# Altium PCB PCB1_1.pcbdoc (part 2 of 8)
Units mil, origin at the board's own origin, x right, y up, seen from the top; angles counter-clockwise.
Board outline 3937.01 x 3346.46 mil, 6 copper layers (Top Layer, Signal-1, SIG, POWER, Signal-4, Bottom Layer), stack 60.565 mil thick; 256 components, 201 nets, 1360 pads, 815 vias.
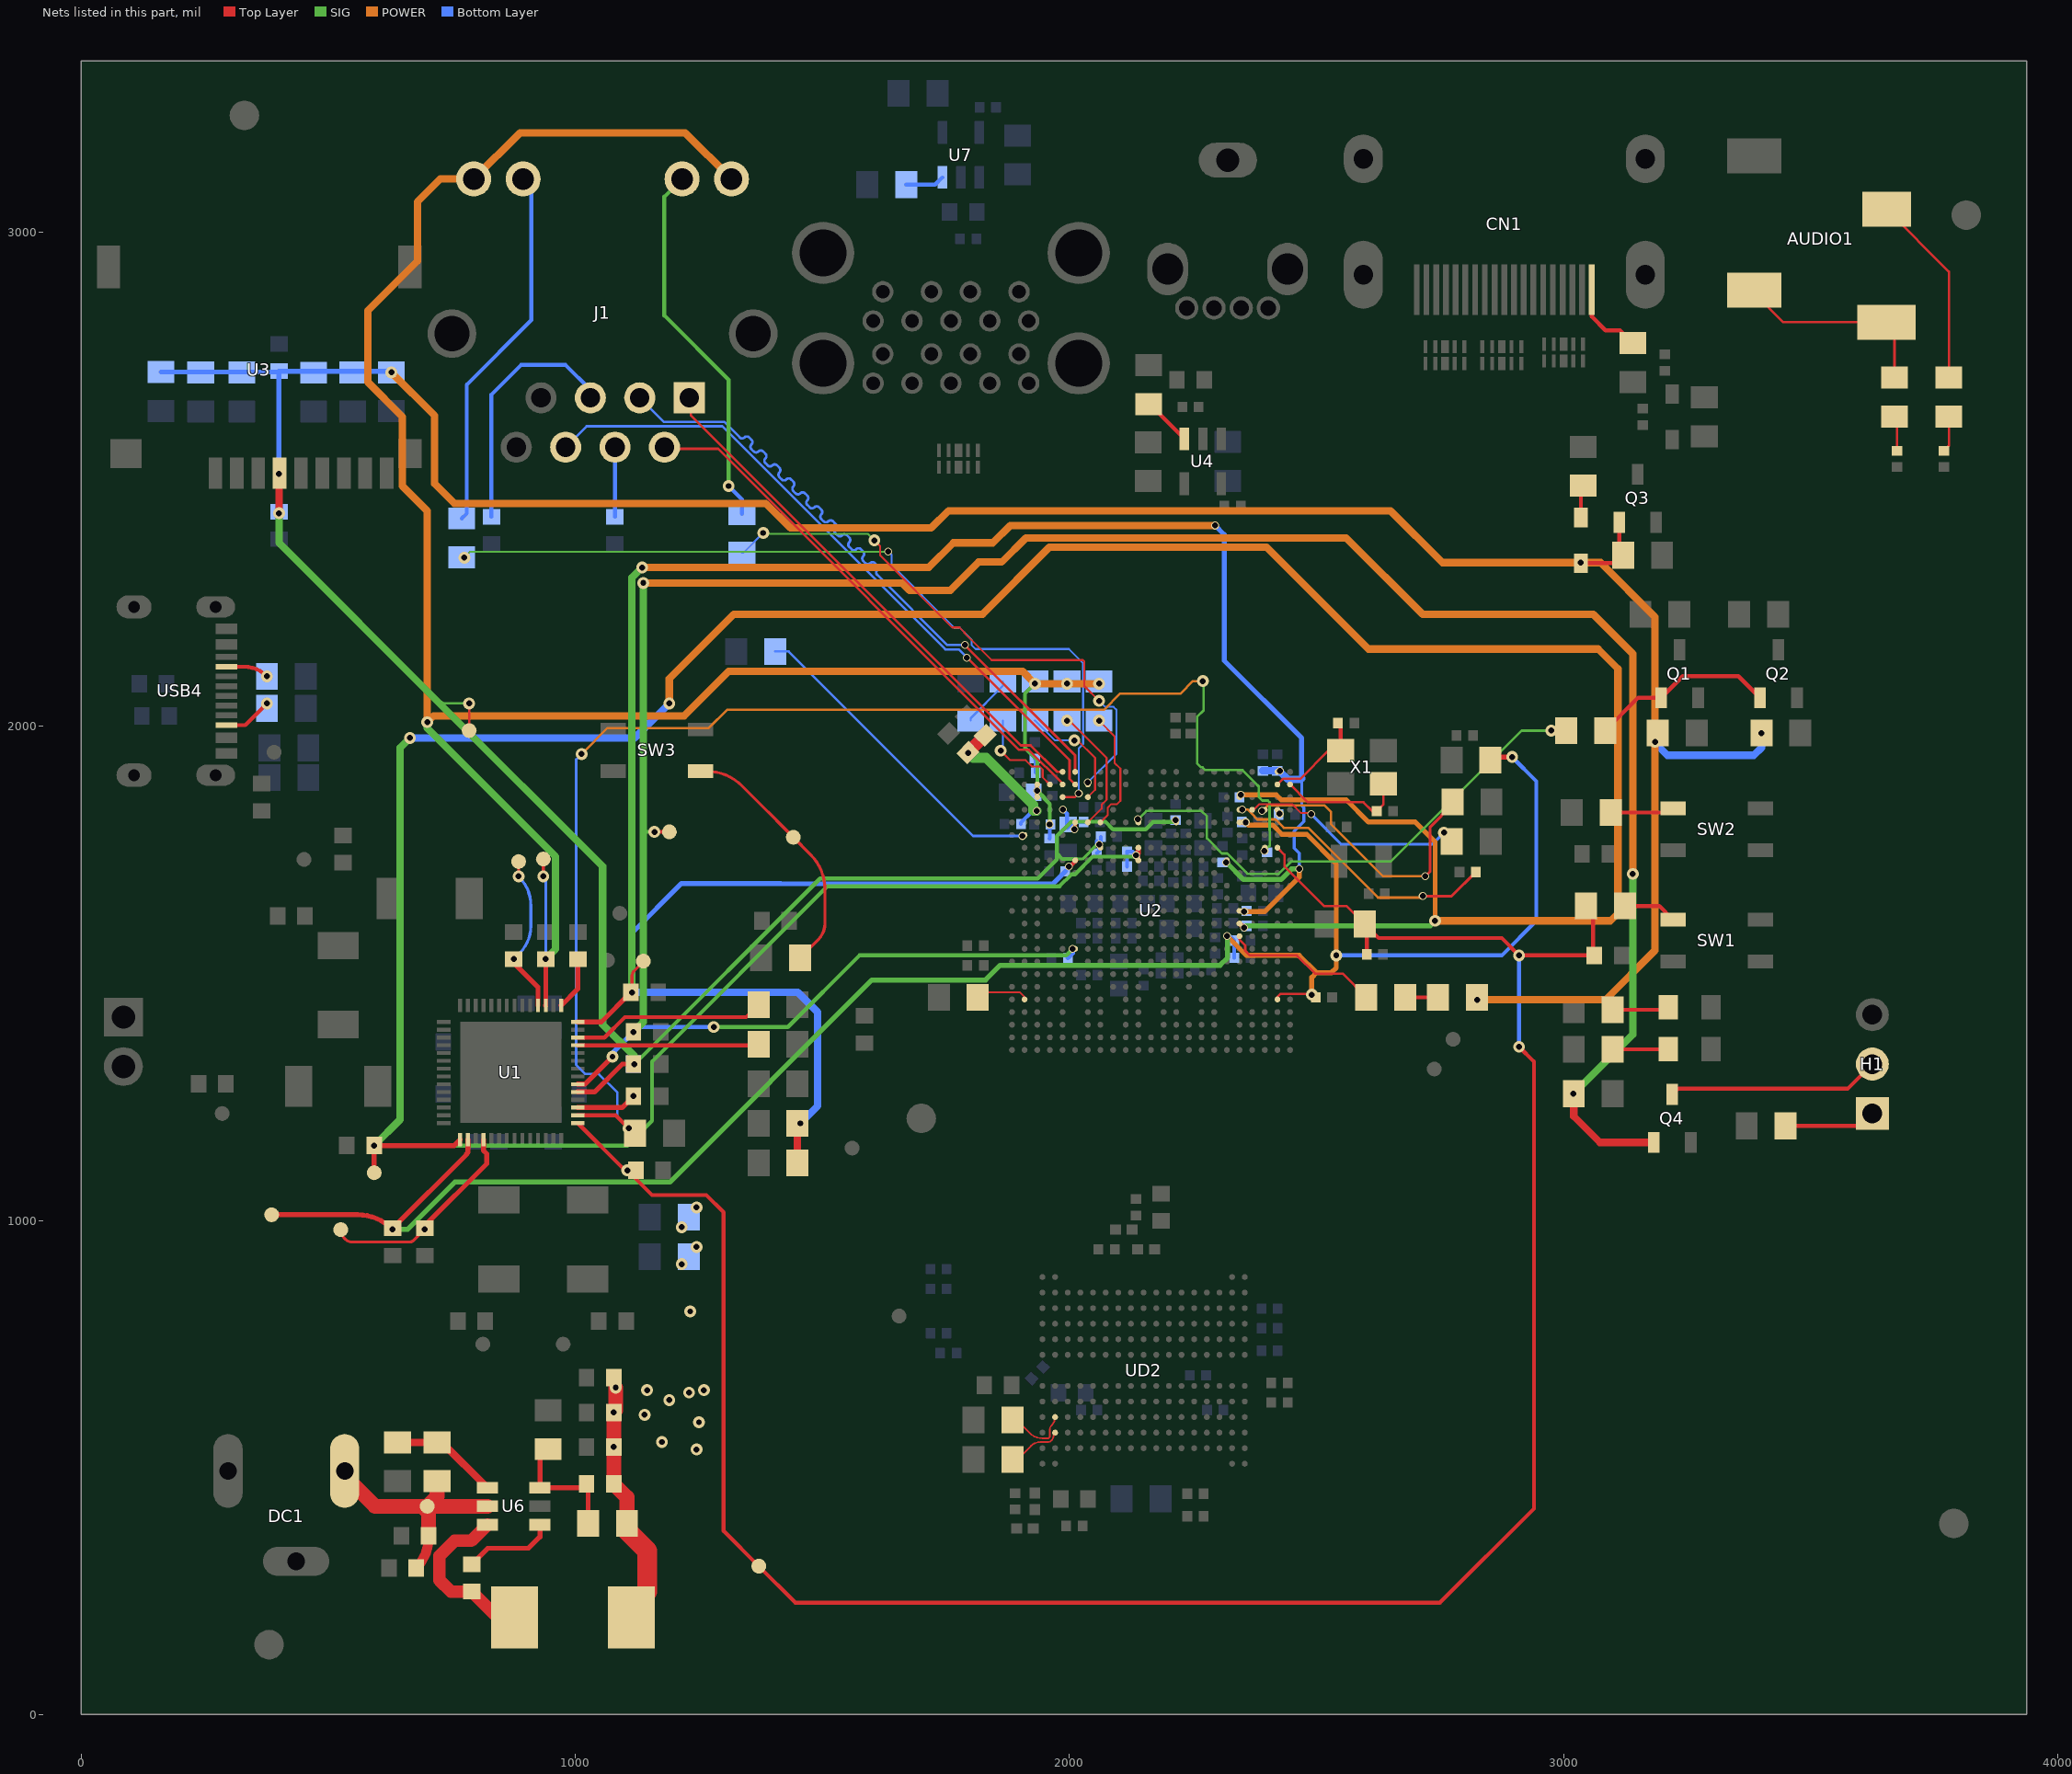
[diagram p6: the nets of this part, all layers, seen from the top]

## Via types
v1: diameter 16, hole 12, Top Layer to Bottom Layer, 426 vias
v2: diameter 24, hole 12, Top Layer to Bottom Layer, 385 vias
v3: diameter 34, hole 12, Top Layer to Bottom Layer, 2 vias
v4: diameter 30, hole 12, Top Layer to Bottom Layer, 2 vias

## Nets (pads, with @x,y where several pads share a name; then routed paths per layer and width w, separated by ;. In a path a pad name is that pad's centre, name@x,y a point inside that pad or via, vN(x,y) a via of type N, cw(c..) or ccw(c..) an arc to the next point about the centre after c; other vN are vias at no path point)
$1N47: R17.2 U2.W2 | length 108.9
  Top Layer w4: R17.2@1814.37,1451.46 1814.37,1453.22 1823.16,1462.01 1899.08,1462.01 1909.09,1451.99 U2.W2@1909.09,1447.36
$1N119: R18.1 UD2.B3 | length 110.3
  Top Layer w3.5: R18.1@1884.37,516.46 ccw(c1884.37,542.12) 1902.52,523.97 1922.27,543.73 cw(c1940.93,525.08) 1940.93,551.46 1951.78,551.46 ccw(c1951.78,551.62) 1951.9,551.5 1955.78,551.48 ccw(c1955.78,563.21) 1964.07,554.92 ccw(c1955.78,563.21) 1967.5,563.21 cw(c1976.91,563.21) 1970.26,569.86 UD2.B3@1970.87,570.47
$1N172: R30.1 UD2.B4 | length 132.8
  Top Layer w3.5: R30.1@1884.37,596.46 cw(c1884.37,576.77) 1898.29,590.69 1919.39,569.59 ccw(c1945,595.2) 1945,558.98 1955.78,558.98 ccw(c1955.78,563.21) 1958.76,560.22 ccw(c1955.78,563.21) 1960,563.21 1960,575.74 cw(c1973.81,575.74) 1964.05,585.5 ccw(c1947.58,601.97) UD2.B4@1970.87,601.97
$2N7: C137.2 J1.4 | length 141.1
  Bottom Layer w8: C137.2@1080,2424.02 1080,2564.8 J1.4@1080.2,2565
$2N9: C138.2 J1.5 | length 509.5
  Bottom Layer w8: C138.2@830,2424.02 830,2671.46 890,2731.46 980,2731.46 1030.2,2681.26 J1.5@1030.2,2665
$2N15: J1.10 R45.2 | length 757.9
  SIG w8: J1.10@1215.83,3107.91 1180,3072.08 1180,2831.46 1310,2701.46 v2(1310,2486.46)
  Bottom Layer w8: v2(1310,2486.46) 1337.04,2459.42 R45.2@1337.04,2429.91
$2N16: J1.11 R46.2 | length 752.3
  Bottom Layer w8: R46.2@770,2420.83 780,2430.83 780,2691.46 910.77,2822.23 910.77,3091.31 J1.11@894.17,3107.91
$2N51: CN1.19 R47.2 | length 159.9
  Top Layer w8: CN1.19@3057.15,2884.17 3057.15,2829.3 3085,2801.46 3114.37,2801.46 R47.2@3140,2775.83
$2N63: Q1.1 Q2.1 R48.2 | length 376.9
  Top Layer w8: R48.2@3084.37,1991.46 3150.74,2057.83 Q1.1@3197.6,2057.83 3241.23,2101.46 3353.98,2101.46 Q2.1@3397.6,2057.83
$2N73: D4.1 R54.2 | length 66.5
  Top Layer w8: D4.1@3035,2422.62 3035,2482.09 R54.2@3040,2487.09
$3N65: R4.2 U1.25 | length 366.6
  Top Layer w8: U1.25@1004.84,1354.46 1368.63,1354.46 R4.2@1370.63,1356.46
$3N68: R5.2 U1.26 | length 393.2
  Top Layer w8: U1.26@1004.84,1370.21 1058.75,1370.21 1100,1411.46 1345.63,1411.46 R5.2@1370.63,1436.46
$3N119: C25.1 U1.29 | length 107.7
  Top Layer w10: U1.29@971.38,1435.16 1005,1468.78 C25.1@1005,1528.9
$4N2: R8.2 R12.1 | length 66.3
  Top Layer w8: R12.1@2679.37,1451.46 R8.2@2745.63,1451.46
$4N5: R12.2 U2.P19 | length 318.3
  Top Layer w5: U2.P19@2344.13,1575.28 2344.13,1568.2 2355.54,1556.8 2355.54,1545.92 2365,1536.46 2460,1536.46 2497,1499.46 2552.63,1499.46 R12.2@2600.63,1451.46
$4N31: R23.1 U2.F2 | length 655.5
  Bottom Layer w5: R23.1@1404.28,2151.58 1431.62,2151.58 1805,1778.19 v1(1905.11,1778.19)
$5N38: R66.2 U2.B4 | length 200.1
  Top Layer w4: v2(1860.62,1950.84) 1880,1931.46 1911.18,1931.46 1923.78,1918.86 1939.2,1918.86 1945.59,1912.47 1945.59,1897.05 U2.B4@1960.28,1882.36
  Bottom Layer w4: v2(1860.62,1950.84) 1865,1955.22 R66.2@1865,2012.09
$5N74: R9.1 U2.E8 | length 247.3
  Top Layer w4: v2(2060,2011.46) 2091.5,1979.96 2091.5,1925.86 2102.91,1914.45 2102.91,1849.37 2095.63,1842.09 2083.71,1842.09 2077.32,1835.7 2077.32,1820.28 U2.E8@2062.64,1805.59
$5N75: R10.1 U2.C7 | length 238.8
  Top Layer w4: v2(2010,1971.46) 2016.73,1971.46 2051.73,1936.46 2051.73,1871.46 U2.C7@2037.05,1856.77
  Bottom Layer w4: R10.1@1930,2012.09 1970.63,1971.46 v2(2010,1971.46)
$5N76: R1.1 U2.E7 | length 257.7
  Top Layer w4: v2(1995,2011.46) 2000,2011.46 2075,1936.46 2075,1851.46 2065,1841.46 2065,1833.54 U2.E7@2037.05,1805.59
$5N200: R65.2 R66.1 | length 105.7
  Bottom Layer w4: R65.2@1800,2012.09 1800,2016.46 1865,2081.46 R66.1@1865,2090.83
$8N79: R58.2 SW1.1 | length 108.5
  Top Layer w8: R58.2@3124.37,1636.46 3193.74,1636.46 SW1.1@3221.42,1608.78
$8N84: R59.2 SW2.1 | length 129.5
  Top Layer w8: R59.2@3095.25,1825.66 3213.3,1825.66 SW2.1@3221.42,1833.78
$8N87: pad.1@1440.99,1775.46 R60.2 SW3.1 | length 720.4
  Top Layer w6: SW3.1@1253.58,1909.13 1265.9,1909.13 cw(c1265.9,1809.13) 1336.61,1879.84 ; R60.2@1454.37,1531.46 1491.3,1568.39 ccw(c1458.24,1601.46) 1505,1601.46 1505,1670.04 ccw(c1405,1670.04) 1475.71,1740.75 ; 1336.61,1879.84 1475.71,1740.75 ; 1336.61,1879.84 pad.1@1440.99,1775.46 1475.71,1740.75
$8N99: H1.1 R61.2 | length 186
  Top Layer w8: R61.2@3449.37,1191.46 3600,1191.46 H1.1@3625,1216.46
$8N102: H1.2 Q4.3 | length 430.4
  Top Layer w8: Q4.3@3220,1255.08 3231.38,1266.46 3575,1266.46 H1.2@3625,1316.46
$8N104: LED1.2 R50.2 | length 112.3
  Top Layer w8: R50.2@3099.37,1346.46 LED1.2@3211.69,1346.46
$8N105: LED2.2 R51.2 | length 114.4
  Top Layer w8: R51.2@3099.37,1426.46 3206.69,1426.46 LED2.2@3211.69,1431.46
$9N31: R24.2 U4.3 | length 101.7
  Top Layer w8: R24.2@2160,2652.09 2162.39,2652.09 U4.3@2232.6,2581.88
$9N44: R55.2 U7.3 | length 79.3
  Bottom Layer w8: R55.2@1669.37,3096.46 1728.02,3096.46 U7.3@1742.6,3111.04
$9N87: R38.2 USB4.B5 | length 100.3
  Top Layer w8: USB4.B5@293.51,2002.56 331.72,2002.55 v2(375.63,2046.46)
$9N88: R37.2 USB4.A5 | length 87.3
  Top Layer w8: USB4.A5@293.51,2120.67 329.26,2120.66 cw(c329.26,2055.09) v2(375.63,2101.46)
$9N98: C133.1 U6.1 | length 185.6
  Top Layer w10: C133.1@790,304.02 822.43,336.46 905,336.46 928.15,359.61 U6.1@928.15,384.06
$9N120: C146.1 R64.1 | length 71.2
  Top Layer w5: R64.1@3670,2627.09 3675,2622.09 C146.1@3675,2558
$9N121: C145.1 R63.1 | length 73.2
  Top Layer w5: C145.1@3770,2558 3780,2568 R63.1@3780,2627.09
$9N123: AUDIO1.3 R63.2 | length 392.9
  Top Layer w5: AUDIO1.3@3653.85,3046.49 3780,2920.34 R63.2@3780,2705.83
$9N124: AUDIO1.2 AUDIO1.4 R64.2 | length 417.2
  Top Layer w5: AUDIO1.2@3386.14,2883.11 3386.14,2877.01 3445,2818.15 AUDIO1.4@3653.86,2818.15 3670,2802.01 R64.2@3670,2705.83
AC-AVCC: C30.2 C42.2 C63.2 U2.D3 | length 288.4
  Top Layer w25: C30.2@1794.49,1946.97 C63.2@1829.49,1981.97
  SIG w20: v2(1795,1946.46) 1805,1936.46 1831.15,1936.46 1926.5,1841.11 1926.5,1829.6 1927.17,1828.93 v1(1933.78,1828.93)
  Bottom Layer w8: C42.2@1901.56,1802.36 1901.56,1804.93 1925.56,1828.93 v1(1933.78,1828.93)
AC-LDOIN: C17.2 C35.2 C40.2 C47.2 C53.2 C66.2 J1.9 J1.12 pad.1@935,1731.46 R1.2 R9.2 R10.2 U1.31 U2.B3 U2.C3 U2.E4 | length 4618.4
  Top Layer w6: v2(935,1696.46) pad.1@935,1731.46
  Top Layer w8: U2.C3@1934.69,1856.77 U2.B3@1934.69,1882.36
  Top Layer w10: U1.31@939.88,1435.16 940,1435.28 v2(940,1528.9)
  SIG w8: v2(1930,2086.46) 1910,2066.46 1910,1956.46 1934.89,1931.57 v1(1934.89,1869.64) 1949.5,1855.03 1949.5,1853.5 1960,1843 v1(1960,1801.46)
  SIG w15: v2(700,2008.46) 700,1996.46 960,1736.46 960,1548.9 v2(940,1528.9)
  POWER w15: J1.9@1315.83,3107.91 1222.28,3201.46 887.72,3201.46 J1.12@794.17,3107.91 726.45,3107.91 680,3061.46 680,2941.46 580,2841.46 580,2696.46 650,2626.46 650,2486.46 700,2436.46 v2(700,2008.46) 713,2021.46 1220,2021.46 1310,2111.46 1905,2111.46 v2(1930,2086.46) v2(1995,2086.46) v2(2060,2086.46)
  Bottom Layer w6: v2(935,1696.46) cw(c922.93,1684.39) 940,1684.39 v2(940,1528.9)
  Bottom Layer w8: C47.2@1930,1934.92 1931.54,1933.38 C66.2@1931.54,1906.46 1934.89,1903.11 v1(1934.89,1869.64) ; C35.2@1959.73,1773 1960,1773.27 v1(1960,1801.46)
AC-VDD-IN: C54.2 C55.2 U2.D5 U2.E6 | length 94.1
  Top Layer w8: v1(2010,1791.46) 2011.46,1792.91 U2.E6@2011.46,1805.59
  Bottom Layer w8: v1(1986.69,1831.37) 1995,1823.06 1995,1794.02 2007.44,1806.46 C55.2@2028.46,1806.46
ALDO1: C18.2 C41.2 C52.2 C58.2 C64.2 C67.2 pad.1@1137.41,1524.91 R2.1 R3.1 U1.28 U2.A22 U2.H6 U2.H18 U2.M19 | length 5272.4
  Top Layer w6: v2(1114.41,1461.46) 1114.41,1492.96 cw(c1133.5,1492.96) 1120,1506.46 1136.67,1523.12 ccw(c1134.88,1524.91) pad.1@1137.41,1524.91
  Top Layer w8: v1@1996.79,1715.59 2000.59,1715.59 U2.H6@2014.22,1729.22
  Top Layer w10: U1.28@1004.84,1401.7 1052.68,1401.7 C18.2@1112.44,1461.46 ; U2.M19@2344.13,1626.46 2352.62,1626.46 v1(2353.76,1625.32)
  Top Layer w15: R2.1@1449.37,1116.46 1449.37,1190.83 v2(1455,1196.46)
  SIG w10: v1(2317.32,1724.64) 2352,1689.96 2428.05,1689.96 2449.47,1711.38 v1(2464.92,1711.38)
  SIG w15: v2(1114.41,1461.46) 1114.41,2300.87 v2(1135,2321.46)
  POWER w10: v1(2353.76,1625.32) 2395.52,1625.32 2464.92,1694.71 v1(2464.92,1711.38)
  POWER w15: v2(1135,2321.46) 1715,2321.46 1765,2371.46 1845,2371.46 1880,2406.46 v1(2295,2406.46)
  Bottom Layer w6: v1(2464.92,1711.38) 2464.92,1743.2 2454.92,1753.2 2454.92,1788.05 2474.38,1807.51 2474.38,1835.4 2470,1839.78 2470,1894.59
  Bottom Layer w8: C67.2@1991.54,1706.46 1996.79,1711.7 C67.2@1996.79,1715.59
  Bottom Layer w10: v2(1114.41,1461.46) 1114.41,1581.35 1215,1681.94 1415.49,1681.94 1415.97,1681.46 1966.54,1681.46 C67.2@1991.54,1706.46 ; v1(2295,2406.46) 2313.19,2388.27 2313.19,2133.27 2470,1976.46 2470,1894.59
  Bottom Layer w15: v2(1114.41,1461.46) 1450,1461.46 1490,1421.46 1490,1231.46 v2(1455,1196.46) ; C64.2@2391.34,1909.92 v1(2425.98,1909.92) 2425.98,1908.61 2442.13,1892.46 2467.87,1892.46 2470,1894.59
  other v1: 1998.39,1716.02
ALDO3: C20.2 pad.1@885,1726.46 U1.32 | length 329.5
  Top Layer w6: v2(885,1696.46) pad.1@885,1726.46
  Top Layer w10: v2(875,1528.9) 875,1521.46 924.14,1472.31 U1.32@924.14,1435.16
  Bottom Layer w6: v2(875,1528.9) 886.98,1540.87 ccw(c831.39,1596.46) 910,1596.46 910,1636.1 ccw(c824.64,1636.1) v2(885,1696.46)
AP-NMI: C83.2 R56.2 U1.16 U2.G21 | length 2721.4
  Top Layer w8: U1.16@1004.84,1212.73 1081.41,1212.73 v2(1107.68,1186.46)
  SIG w5: v2(2270,2091.46) 2271.46,2089.99 2271.46,2032.22 2258.36,2019.12 2258.36,1925.36 2266.56,1917.15 2269.3,1917.15 2275,1911.46 2350,1911.46 2375,1886.46 2375,1886.31 2383.13,1878.18 2383.13,1856.86 2390,1849.99 2401.46,1849.99 2405,1846.46 2405,1789.7 2405.26,1789.44 2405.26,1758.29 v1(2394.7,1747.73)
  POWER w5: v2(1012.5,1943.96) 1065,1996.46 1270,1996.46 1307,2033.46 2069.86,2033.46 2102.86,2066.46 2225,2066.46 2250,2091.46 v2(2270,2091.46)
  Bottom Layer w5: v2(1012.5,1943.96) 1001.46,1932.92 1001.46,1314.99 1020,1296.46 1046.98,1296.46 1085,1258.44 1085,1209.13 v2(1107.68,1186.46)
AP-RESET: C11.2 C84.2 C142.1 pad.5 R11.2 R58.1 U1.15 U2.G22 | length 4853.3
  Top Layer w5: U2.G22@2420.91,1754.41 2435,1740.31 2435,1716.58 2515.12,1636.46 2560.84,1636.46 R11.2@2597.3,1599.99
  Top Layer w8: U1.15@1004.84,1196.98 1100.36,1101.46 v2(1105,1101.46) 1155,1051.46 1265,1051.46 1300,1016.46 1300,371.46 pad.5@1371.23,300.22 1445,226.46 2750,226.46 2940,416.46 2940,1321.46 v2(2910,1351.46) ; C84.2@2601.73,1538.47 2601.73,1595.57 2625.84,1571.46 2875,1571.46 v2(2910,1536.46) C142.1@3062.44,1536.46 3060,1538.9 3060,1622.09 R58.1@3045.63,1636.46
  Top Layer w10: v2(1105,1101.46) C11.2@1122.44,1101.46
  Top Layer w15: R11.2@2597.3,1599.99 R11.2@2601.73,1595.57
  Bottom Layer w8: v2(2910,1351.46) v2(2910,1536.46)
BIAS-ITEST: R7.1 U2.D20 | length 460.7
  Top Layer w4: U2.D20@2369.72,1831.18 2373,1831.18 2384.41,1842.59 2450.51,1842.59 2468.67,1824.43 2484.67,1824.43 2486.64,1822.46 v1(2488.88,1822.46)
  Top Layer w6: v2(2757.98,1784.89) 2773.54,1769.33 R7.1@2773.54,1767.18
  Bottom Layer w6: v1(2488.88,1822.46) 2550.16,1761.18 2734.27,1761.18 v2(2757.98,1784.89)
BIAS-REXT: R67.1 U2.D21 | length 582.1
  Top Layer w6: v1(2720,1696.46) 2730,1706.46 2730,1796.46 2775.29,1841.75 R67.1@2775.29,1847.21
  POWER w5: v1(2390,1829.09) 2400.87,1839.96 2516.3,1839.96 2529,1827.26 2529,1802.46 2635,1696.46 v1(2720,1696.46)
BIAS-VRAL: C85.2 U2.D19 | length 568.2
  Top Layer w6: v1(2715,1656.46) 2773.58,1656.46 C85.2@2822.52,1705.39
  POWER w5: v1(2350,1831.46) 2361.05,1831.46 2375,1817.5 ; 2375.04,1817.47 2375.04,1816.61 2380,1811.64 2416.9,1811.64 2433.96,1794.59 2483.13,1794.59 2624.26,1653.46 2712,1653.46 v1(2715,1656.46)
BLDO1: C2.2 C31.2 C39.2 C51.2 C108.2 pad.1@385,1011.46 R14.2 U1.2 U2.E19 U2.P18 U2.W22 | length 4167.8
  Top Layer w5: U2.W22@2420.91,1447.32 2420.91,1452.36 2427.27,1458.73 2488.64,1458.73 v2(2490.46,1456.91)
  Top Layer w10: pad.1@385,1011.46 559.17,1011.46 cw(c559.17,911.46) 629.88,982.17 v2(630,982.05) ; C2.2@630,984.02 779.5,1133.52 779.5,1134.95 782.4,1137.85 U1.2@782.4,1163.51 ; U2.E19@2344.13,1805.59 2356.15,1805.59 v1(2356.56,1806) ; R14.2@2852.13,1931.79 2858.26,1937.92 v2(2896,1937.92)
  SIG w10: v2(630,982.05) 660.59,982.05 756.02,1077.47 1191.02,1077.47 1600,1486.46 1830,1486.46 1859.84,1516.29 2304.84,1516.29 2320,1531.46 2320,1574.49 v1(2318.63,1575.87)
  POWER w10: v1(2318.63,1575.87) 2358.04,1536.46 2465,1536.46 2500,1501.46 ; v1(2356.56,1806) 2362.42,1800.14 2411.31,1800.14 2430,1781.46 2480,1781.46 2540,1721.46 v2(2540,1536.46) 2540,1511.46 2530,1501.46 2500,1501.46 ; v2(2490.46,1456.91) 2490.46,1491.91 2500,1501.46
  Bottom Layer w8: v1(2318.63,1575.87) 2324.05,1575.87 C31.2@2333.46,1566.46 C108.2@2333.46,1531.46 ; v2(2540,1536.46) 2875,1536.46 2945,1606.46 2945,1888.92 v2(2896,1937.92)
BLDO2: C1.2 C43.2 C44.2 C59.2 C90.2 pad.1@592.56,1096.46 U1.1 U2.C19 U2.G11 U2.H11 U2.N19 | length 7631.4
  Top Layer w8: v1(2135,1739.09) 2139.41,1734.68 U2.H11@2139.41,1728.99
  Top Layer w10: pad.1@592.56,1096.46 v2(592.56,1151.46) 754.61,1151.46 U1.1@766.66,1163.51 ; v1(2135,1739.09) 2139.41,1743.5 U2.G11@2139.41,1754.41 ; U2.N19@2344.13,1600.87 2344.63,1600.87 v1(2353.38,1592.11)
  SIG w8: v2(592.56,1151.46) 1105,1151.46 1155,1201.46 1155,1321.46 1510,1676.46 1979.96,1676.46 2003.76,1700.26 2010.72,1700.26 2046.92,1736.46 2132.37,1736.46 v1(2135,1739.09)
  SIG w10: v1(2353.38,1592.11) 2357.73,1596.46 2730,1596.46 v2(2740,1606.46)
  SIG w15: v2(592.56,1151.46) 645,1203.9 645,1956.46 v2(665,1976.46)
  POWER w10: v1(2346.45,1861.46) 2418.21,1861.46 2428.21,1851.46 2560,1851.46 2605,1806.46 2700,1806.46 2740,1766.46 v2(2740,1606.46)
  POWER w15: v2(1190,2046.46) 1190,2096.46 1320.4,2226.86 1823.84,2226.86 1959.44,2362.46 2399,2362.46 2605,2156.46 3070,2156.46 3110,2116.46 3110,1621.46 3095,1606.46 v2(2740,1606.46)
  Bottom Layer w8: C90.2@2116.54,1716.46 C43.2@2116.54,1746.46 2127.63,1746.46 v1(2135,1739.09)
  Bottom Layer w15: v2(665,1976.46) 1120,1976.46 v2(1190,2046.46)
BLDO3: C3.2 pad.1@525,981.35 U1.4 | length 428.8
  Top Layer w6: pad.1@525,981.35 ccw(c548.88,981.35) 532,964.46 535,961.46 ccw(c547.4,973.85) 547.4,956.32 664.68,956.32 ccw(c664.68,956.78) 665,956.46 ccw(c665,967.1) 672.53,959.57 v2(695,982.05)
  Top Layer w10: C3.2@695,984.02 695,989.47 820.5,1114.97 820.5,1134.95 813.9,1141.55 U1.4@813.9,1163.51
CLDO1: C13.2 C26.2 C33.2 C37.2 C123.1 C130.2 C147.2 D4.2 pad.1@785,1991.46 Q3.1 R8.1 R25.2 R26.2 R27.2 R28.2 R29.2 R49.1 R52.1 R53.2 R57.2 U1.19 U2.E14 U2.G8 U3.4 | length 8278.6
  Top Layer w5: pad.1@785,1991.46 v2(785,2046.46)
  Top Layer w8: D4.2@3035,2330.3 3104.47,2330.3 R53.2@3120.63,2346.46 3112.6,2354.49 Q3.1@3112.6,2412.83
  Top Layer w10: U1.19@1004.84,1259.97 1038.51,1259.97 1095,1316.46 C13.2@1117.44,1316.46
  Top Layer w15: v2(400,2431.46) v2(400,2511.46)
  SIG w5: 727.52,2043.94 cw(c733.6,2037.85) 733.6,2046.46 v2(785,2046.46)
  SIG w6: 2015,1731.46 2026.36,1731.46 2055.77,1760.86 v1(2060.31,1760.86)
  SIG w8: v2(1119.41,1316.46) 1495.07,1692.11 1935.66,1692.11 1974.5,1730.96 1974.5,1742.37 ; 2015,1731.46 1985.35,1731.52 1974.5,1742.37 ; v1(2215,1809.92) 2211.45,1806.36 2169.17,1806.36 2154.27,1791.46 2088.08,1791.46 2072.58,1806.96 2003.58,1806.96 1974.5,1777.88 1974.5,1742.37
  SIG w15: v2(400,2431.46) 400,2371.46 727.52,2043.94 1055,1716.46 1055,1396.46 1119.41,1332.05 v2(1119.41,1316.46) v2@1119.1,1316.15
  POWER w15: v2(627.65,2716.52) 715,2629.17 715,2491.46 755,2451.46 1385,2451.46 1435,2401.46 1720,2401.46 1755,2436.46 2650,2436.46 2755,2331.46 v2(3035,2331.46) 3075,2331.46 3185,2221.46 v2(3185,1968.46) 3185,1546.46 3085,1446.46 v2(2825,1446.46)
  Bottom Layer w8: C26.2@2055,1743 2060.31,1748.31 v1(2060.31,1760.86) 2063.46,1764 C37.2@2063.46,1776.46 ; v1@2055,1760.86 C37.2@2055,1768
  Bottom Layer w10: R25.2@161.03,2717.23 C123.1@398.34,2717.23 ; v2(400,2511.46) 400,2714.99 398.34,2716.65 C123.1@398.34,2717.23 ; v2(627.65,2716.52) 625.27,2718.9 C123.1@400,2718.9 C123.1@398.34,2717.23
  Bottom Layer w15: v2(3185,1968.46) 3185,1966.46 3210,1941.46 3385,1941.46 3400.61,1957.06 v2(3400.61,1986.46)
CLDO2: C14.2 C36.2 pad.1@1190,1786.46 Q4.1 R62.1 U1.20 U2.R6 | length 5431.3
  Top Layer w8: v2(1160,1786.46) pad.1@1190,1786.46
  Top Layer w10: U1.20@1004.84,1275.72 1019.26,1275.72 v2(1075,1331.46)
  Top Layer w15: R62.1@3020.63,1256.46 3020.63,1210.83 3073.62,1157.83 Q4.1@3182.6,1157.83
  SIG w8: 1137.41,1785.01 cw(c1140.91,1781.51) 1140.91,1786.46 v2(1160,1786.46) ; v2(1280,1391.46) 1430,1391.46 1575,1536.46 1993.23,1536.46 v1(2006.46,1549.69)
  SIG w15: v2(1117.44,1381.46) 1137.41,1401.43 1137.41,1785.01 v2(1137.41,2290.19) ; v2(3020,1256.46) 3140,1376.46 v2(3140,1701.46)
  POWER w15: v2(1137.41,2290.19) 1661.26,2290.19 1676.26,2275.19 1758.74,2275.19 1816,2332.46 1862.77,2332.46 1911.77,2381.46 2560,2381.46 2715,2226.46 3060,2226.46 3140,2146.46 v2(3140,1701.46)
  Bottom Layer w8: v2(1117.44,1381.46) 1127.44,1391.46 v2(1280,1391.46)
  Bottom Layer w10: v2(1075,1331.46) 1075,1339.02 v2(1117.44,1381.46) ; C36.2@1996.54,1531.46 2006.46,1541.37 v1(2006.46,1549.69)
CLDO3: C29.2 U1.17 | length 122.1
  Top Layer w10: U1.17@1004.84,1228.47 1094.45,1228.47 v2(1117.44,1251.46)
DC-5V: C24.2 C134.1 C135.2 C136.2 L6.2 R41.2 R42.2 R43.2 | length 507.8
  Top Layer w30: v2(1081.5,661.46) 1081.5,615.39 v2(1077.56,611.46) v2(1077.56,541.46) C134.1@1077.56,466.46 1104.37,439.65 R43.2@1104.37,386.46
  Top Layer w40: R43.2@1104.37,386.46 1104.37,372.09 1145,331.46 1145,248.34 1113.11,216.46 L6.2@1113.11,196.46
  other v2: 1245,536.46 1175,551.46 1250,591.46 1140,606.46 1190,636.46 1230,651.46 1145,656.46 1260,656.46 1232.32,815.83 1215,911.46 1245,946.46 1215,986.46 1245,1026.46
DC-EN: R15.1 R16.2 U6.4 | length 219.9
  Top Layer w15: R16.2@640,550.83 R15.1@720,550.83 729.88,550.83 U6.4@821.85,458.86
DC-SW: C133.2 L6.1 U6.6 | length 355.7
  Top Layer w25: U6.6@821.85,384.06 789.25,351.46 755,351.46 725,321.46 725,271.46 747.56,248.9 C133.2@790,248.9 842.44,196.46 L6.1@876.89,196.46
DC-VIN: C141.2 C148.2 DC1.1 pad.1@700,421.46 R15.2 U6.5 | length 512.7
  Top Layer w20: C148.2@677.56,296.46 ccw(c617.2,356.81) C141.2@702.56,356.81
  Top Layer w30: DC1.1@533.15,493.01 533.11,482.63 594.28,421.46 690,421.46 pad.1@695,416.46 ; C141.2@702.56,361.46 702.56,408.9 pad.1@695,416.46 ; R15.2@720,472.09 720,441.46 pad.1@700,421.46 ; U6.5@821.85,421.46 pad.1@700,421.46 ; pad.1@695,416.46 pad.1@700,421.46
DCDC-FB: C134.2 R43.1 R44.2 U6.3 | length 264
  Top Layer w10: R44.2@945,537.09 928.15,520.24 U6.3@928.15,458.86 1014.84,458.86 C134.2@1022.44,466.46 1025.63,463.27 R43.1@1025.63,386.46
DCXO-LDOOUT: C65.2 U2.D22
  other v1: 2425.43,1822.92
DCXO-XIN: C86.1 U2.B23 X1.4 | length 258.9
  Top Layer w5: U2.B23@2446.5,1882.36 2482.4,1846.46 2595,1846.46 2613,1828.46 C86.1@2621.93,1828.46 2635.31,1841.84 X1.4@2635.31,1884.07
DCXO-XOUT: C87.1 U2.B22 X1.2 | length 213.8
  Top Layer w5: U2.B22@2420.91,1882.36 2432.31,1893.77 2467.31,1893.77 2524.54,1951 X1.2@2548.69,1951
  Top Layer w8: C87.1@2543.46,2006.46 2548.69,2001.22 X1.2@2548.69,1951
DDC_CEC_EN: R48.1 U2.E11 | length 1073.3
  Top Layer w5: v2(2975,1991.46) R48.1@3005.63,1991.46
  SIG w5: v1(2138.51,1811.92) 2155.38,1828.8 2267.66,1828.8 2278.11,1818.35 2278.11,1773.35 2308.54,1742.92 2319.04,1742.92 2360.5,1701.46 2423.28,1701.46 2448.28,1726.46 2650,1726.46 2915,1991.46 v2(2975,1991.46)
EPHY-LNK-LED: R45.1 U2.B7 | length 1138.9
  Top Layer w4: v2(1605,2376.46) 1616.96,2364.5 1616.96,2345.85 1762.62,2200.19 1777.25,2200.19 1787.5,2189.93 1787.5,2188.96 1842.17,2134.29 2027.17,2134.29 2030,2131.46 2030,2081.46 v2(2060,2051.46) ; U2.B7@2037.05,1882.36 v1(2037.05,1886.46)
  SIG w4: v2(1380,2391.46) 1381.5,2389.96 1591.5,2389.96 v2(1605,2376.46)
  Bottom Layer w4: R45.1@1337.04,2351.17 1339.71,2351.17 v2(1380,2391.46) ; v1(2037.05,1886.46) 2095,1944.41 2095,2033.56 2089.18,2039.38 2072.08,2039.38 v2(2060,2051.46)
EPHY-RXN: J1.6 U2.B6 | length 1371.2
  Top Layer w5: v1(1792.5,2138.96) 2000,1931.46 2000,1893.82 U2.B6@2011.46,1882.36
  Bottom Layer w5: J1.6@980.2,2565 1022.66,2607.46 1297.17,2607.46 1748.94,2155.69 1775.77,2155.69 v1(1792.5,2138.96)
EPHY-RXP: J1.3 U2.A6 | length 1368.6
  Top Layer w5: v1(1788.23,2164.69) 2011.46,1941.46 U2.A6@2011.46,1907.95
  Bottom Layer w5: J1.3@1130.19,2665 1178.74,2616.46 1300.9,2616.46 1332.57,2584.78 ccw(c1337.35,2589.56) 1342.12,2584.78 cw(c1346.9,2580.01) 1351.67,2584.78 1356.27,2580.19 cw(c1351.49,2575.42) 1356.27,2570.64 ccw(c1361.04,2565.87) 1356.27,2561.09 1360.86,2556.5 ccw(c1365.63,2561.27) 1370.41,2556.5 cw(c1375.18,2551.72) 1379.96,2556.5 1384.55,2551.91 cw(c1379.78,2547.13) 1384.55,2542.36 ccw(c1389.33,2537.58) 1384.55,2532.81 1389.14,2528.21 ccw(c1393.92,2532.99) 1398.69,2528.21 cw(c1403.47,2523.44) 1408.24,2528.21 1412.83,2523.62 cw(c1408.06,2518.85) 1412.83,2514.07 ccw(c1417.61,2509.3) 1412.83,2504.52 1417.43,2499.93 ccw(c1422.2,2504.7) 1426.98,2499.93 cw(c1431.75,2495.15) 1436.53,2499.93 1441.12,2495.34 cw(c1436.34,2490.56) 1441.12,2485.79 ccw(c1445.89,2481.01) 1441.12,2476.24 1445.71,2471.65 ccw(c1450.49,2476.42) 1455.26,2471.65 cw(c1460.04,2466.87) 1464.81,2471.65 1469.4,2467.05 cw(c1464.63,2462.28) 1469.4,2457.5 ccw(c1474.18,2452.73) 1469.4,2447.95 1474,2443.36 ccw(c1478.77,2448.14) 1483.55,2443.36 cw(c1488.32,2438.59) 1493.1,2443.36 1497.69,2438.77 cw(c1492.91,2433.99) 1497.69,2429.22 ccw(c1502.46,2424.44) 1497.69,2419.67 1502.28,2415.08 ccw(c1507.05,2419.85) 1511.83,2415.08 cw(c1516.6,2410.3) 1521.38,2415.08 1525.97,2410.48 cw(c1521.2,2405.71) 1525.97,2400.93 ccw(c1530.75,2396.16) 1525.97,2391.38 1530.56,2386.79 ccw(c1535.34,2391.57) 1540.11,2386.79 cw(c1544.89,2382.02) 1549.66,2386.79 1554.26,2382.2 cw(c1549.48,2377.43) 1554.26,2372.65 ccw(c1559.03,2367.88) 1554.26,2363.1 1558.85,2358.51 ccw(c1563.62,2363.28) 1568.4,2358.51 cw(c1573.17,2353.73) 1577.95,2358.51 1582.54,2353.92 cw(c1577.77,2349.14) 1582.54,2344.37 ccw(c1587.32,2339.59) 1582.54,2334.82 1587.13,2330.22 ccw(c1591.91,2335) 1596.68,2330.22 cw(c1601.46,2325.45) 1606.23,2330.22 1610.82,2325.63 cw(c1606.05,2320.86) 1610.82,2316.08 ccw(c1615.6,2311.31) 1610.82,2306.53 1752.67,2164.69 v1(1788.23,2164.69)
EPHY-SPD-LED: R46.1 U2.C5 | length 1672.6
  Top Layer w4: U2.C5@1985.87,1856.77 2011.19,1856.77 v1(2018.69,1864.27)
  SIG w4: v2(775,2341.46) 787.2,2353.66 v1(1633.33,2353.66)
  Bottom Layer w4: v1(1633.33,2353.66) 1640,2346.99 1640,2326.46 1766.27,2200.19 1777.25,2200.19 1801.73,2175.71 1801.73,2164.73 1810,2156.46 1998.65,2156.46 2027.5,2127.6 2027.5,1964.21 2018.69,1955.4 v1(2018.69,1864.27)
EPHY-TXN: J1.2 U2.B5 | length 1089.6
  Top Layer w5: J1.2@1180.19,2565 1183.42,2561.78 1288.81,2561.78 1898.14,1952.46 1917.73,1952.46 1985.87,1884.32 U2.B5@1985.87,1882.36
EPHY-TXP: J1.1 U2.A5 | length 1087.9
  Top Layer w5: J1.1@1230.2,2665 1233.42,2661.78 1233.42,2629.9 1901.87,1961.46 1921.46,1961.46 1974.96,1907.95 U2.A5@1985.87,1907.95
